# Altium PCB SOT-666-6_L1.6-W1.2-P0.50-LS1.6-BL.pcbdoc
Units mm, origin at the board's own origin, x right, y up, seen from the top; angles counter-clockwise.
Board outline 14.79 x 14.71 mm, 2 copper layers (Top Layer, Bottom Layer), stack 0 mm thick; 1 components, 0 nets, 6 pads, 0 vias.
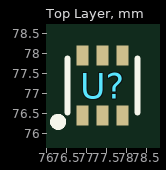
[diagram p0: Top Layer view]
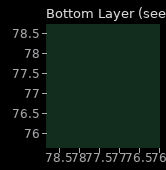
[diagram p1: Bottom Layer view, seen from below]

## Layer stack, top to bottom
Top Layer: signal copper (thickness not stored)
Bottom Layer: signal copper (thickness not stored)

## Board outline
84.638,69.85 69.85,69.85 69.85,84.558 84.638,84.558

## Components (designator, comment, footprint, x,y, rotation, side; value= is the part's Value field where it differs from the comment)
U? "" SOT-666-6_L1.6-W1.2-P0.50-LS1.6-BL 77.411,77.208 r0 top

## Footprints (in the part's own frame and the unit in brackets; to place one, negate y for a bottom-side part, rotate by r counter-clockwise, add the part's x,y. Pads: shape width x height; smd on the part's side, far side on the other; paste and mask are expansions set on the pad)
SOT-666-6_L1.6-W1.2-P0.50-LS1.6-BL [mm]
  rect 0.3x0.5 smd: 1(-0.5,-0.75) 2(0,-0.75) 3(0.5,-0.75) 4(0.5,0.75) 5(0,0.75) 6(-0.5,0.75)
  silkscreen extent -1.21,-1.01 0.88,0.68

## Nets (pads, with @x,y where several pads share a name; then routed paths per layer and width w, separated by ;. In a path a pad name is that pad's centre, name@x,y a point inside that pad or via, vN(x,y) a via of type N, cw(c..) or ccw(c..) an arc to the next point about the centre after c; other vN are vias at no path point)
pads on no net: U?.1 U?.2 U?.3 U?.4 U?.5 U?.6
